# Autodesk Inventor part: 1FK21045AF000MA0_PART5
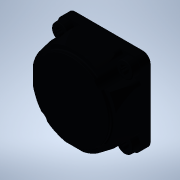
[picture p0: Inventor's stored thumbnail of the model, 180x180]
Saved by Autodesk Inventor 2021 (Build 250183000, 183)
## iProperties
Created: 2025-04
Part Number: 1FK21045AF000MA0_PART5
Material: Generic
Catalog Web Link: www.3dfindit.com
Description: -Servo synchronous motor
Document SubType Name: Modeling
Designer: psAdmin
Mass: 3.92604 g
Surface Area: 17.9521 cm^2
Volume: 3.92604 cm^3
Density: 1 g/cm^3
Appearance: PSOLRGB-48-56-69
Category: PARTsolutions
Title: 1FK21045AF000MA0_PART5
Author: Cadenas PARTsolutions
Comments: Servo synchronous motor
Sending System: PARTsolutions
Preprocessor: ST-DEVELOPER v19.3
PSOL_IDENT_0: {$CADENAS_DATA/23d-libs/siemens_ag/_cat_/8b/0a/1fk21045af000ma0.prj},213 {VTYP=3D},{NB=1FK21045AF000
PSOL_IDENT_1: MA0_PART5},{LINA=1FK21045AF000MA0_PART5},{NN=1FK21045AF000MA0_PART5},{NOPRJ=TRUE},{DATE=19.08.2025 1
PSOL_IDENT_2: 4:00:48},{GEOMDATE=30.07.2025 02:00:28},{VERSION=},{LINEID=10},{WBVAR=},{WBNUMERIC=}  {NB=1FK21045AF
PSOL_IDENT_3: 000MA0_PART5},{LINA=1FK21045AF000MA0_PART5},{KT=DUMMY},{PREVIEW=../../../_pool_/a9/69/p_d211_xx_0081
PSOL_IDENT_4: 8j.png},{DESCSHORT=SIMOTICS S-1FK2 HD, SINAMICS S210 3AC 400V-480V, 2.4 Nm, 3000 rpm},{DESCLONG=SIMO
PSOL_IDENT_5: TICS S-1FK2 HD servo motor M0=2.4 Nm; PN = 0.75 kW at nN=3000 rpm (380-480 V); PN = 0.375 kW at nN=1
PSOL_IDENT_6: 500 rpm (200-240 V); degree of protection IP64; cylindrical shaft D19x40mm; absolute encoder 22-bit
PSOL_IDENT_7: + 12-bit multiturn (encoder AM22DQC); with OCC interface; plug size M17, rotatable; SIMOTICS S-1FK2
PSOL_IDENT_8: servomotorfor a wide range of uses in industrial environments. SIMOTICS S‑1FK2 servomotors are compa
PSOL_IDENT_9: ct synchronous motors with a high dynamic performance that set themselves apart as a result of their
PSOL_IDENT_10: high power density, degree of protection and overload capability. The motors are available in two v
PSOL_IDENT_11: ariants: as High Dynamic variant (highest dynamic performance as a result of the low intrinsic momen
PSOL_IDENT_12: t of inertia for applications demanding a high dynamic performance with low moved masses) - and as C
PSOL_IDENT_13: ompact variant (precise and stable closed-loop control for medium up to large moved masses as a resu
PSOL_IDENT_14: lt of a medium intrinsic moment of inertia). SIMOTICSS‑1FK2 servomotors fully exploit their strength
PSOL_IDENT_15: s in a system with the SINAMICSS210 frequency converter and simple connection using the one cable co
PSOL_IDENT_16: nnection (OCC). Advantages include the short control and positioning times, fast and precise correct
PSOL_IDENT_17: ion of disturbing quantities as well as stable control with a high dynamic performance. The servo mo
PSOL_IDENT_18: tors can be configured to address a wide range of requirements. For example with and without holding
PSOL_IDENT_19: brake, IP64 or IP65 degree of protection, singleturn or multiturn absolute encoders - to name just
PSOL_IDENT_20: a few. Further, the servomotors are available in different shaft heights extending from 20 to 100. A
PSOL_IDENT_21: shaft sealing ring is available to achieve an IP65 degree of protection and for subsequent mounting
PSOL_IDENT_22: at the motor or as spare part. SIMOTICS - the optimum motor for each and every motion control appli
PSOL_IDENT_23: cation.},{INTNO=195125050112},{SUPPLIERALTNO=1FK2104-5AF00-0MA0},{MANUID=1FK21045AF000MA0},{MANUNAME=
PSOL_IDENT_24: Siemens},{MANUTYPEDESC=Synchronous motor 1FK2-HD 2.4 NM},{AAU732=SIMOTICS},{AAO057=S-1FK2},{AAU734=S
PSOL_IDENT_25: IMOTICS S-1FK2 HD servo motor M0=2.4 Nm; PN = 0.75 kW at nN=3000 rpm (380-480 V); PN = 0.375 kW at n
PSOL_IDENT_26: N=1500 rpm (200-240 V); degree of protection IP64; cylindrical shaft D19x40mm; absolute encoder 22-b
PSOL_IDENT_27: it + 12-bit multiturn (encoder AM22DQC); with OCC interface; plug size M17, rotatable;},{AAW338=Sync
PSOL_IDENT_28: hronous motor 1FK2-HD 2.4 NM},{AAO742=SIMOTICS},{AAO663=4042948692912},{NOCUPEROU=1},{PRICEQUANTITY=
PSOL_IDENT_29: 1},{QUANTITYMIN=1},{QUANTITYINT=1},{CTN=85015100},{COO=DE},{AAO676=1FK2104-5AF00-0MA0},{AAO677=Sieme
PSOL_IDENT_30: ns AG},{ORDERUNIT=C62},{CONTENTUNIT=C62}
NB: 1FK21045AF000MA0_PART5
NT: Servo synchronous motor
NBSYN: $MANUID._PART5
LINA: 1FK21045AF000MA0_PART5
CATALOG: SIEMENS
PREVIEW: ../../../_pool_/a9/69/p_d211_xx_00818j.png
DESCSHORT: SIMOTICS S-1FK2 HD, SINAMICS S210 3AC 400V-480V, 2.4 Nm, 3000 rpm
DESCLONG: SIMOTICS S-1FK2 HD servo motor M0=2.4 Nm; PN = 0.75 kW at nN=3000 rpm (380-480 V); PN = 0.375 kW at nN=1500 rpm (200-240 V); degree of protection IP64; cylindri
INTNO: 195125050112
SUPPLIERALTNO: 1FK2104-5AF00-0MA0
MANUID: 1FK21045AF000MA0
MANUNAME: Siemens
MANUTYPEDESC: Synchronous motor 1FK2-HD 2.4 NM
AAU732: SIMOTICS
AAO057: S-1FK2
AAU734: SIMOTICS S-1FK2 HD servo motor M0=2.4 Nm; PN = 0.75 kW at nN=3000 rpm (380-480 V); PN = 0.375 kW at nN=1500 rpm (200-240 V); degree of protection IP64; cylindri
AAW338: Synchronous motor 1FK2-HD 2.4 NM
AAO742: SIMOTICS
AAO663: 4042948692912.0
NOCUPEROU: 1
PRICEQUANTITY: 1
QUANTITYMIN: 1
QUANTITYINT: 1
CTN: 85015100
COO: DE
ARTICLENO: 1FK21045AF000MA0_PART5
BOMINFO: 1FK21045AF000MA0_PART5
CREATOR: CADENAS GmbH
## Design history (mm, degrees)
feature "2025_04_17_15_40_42_0703"
body "Solid1"
